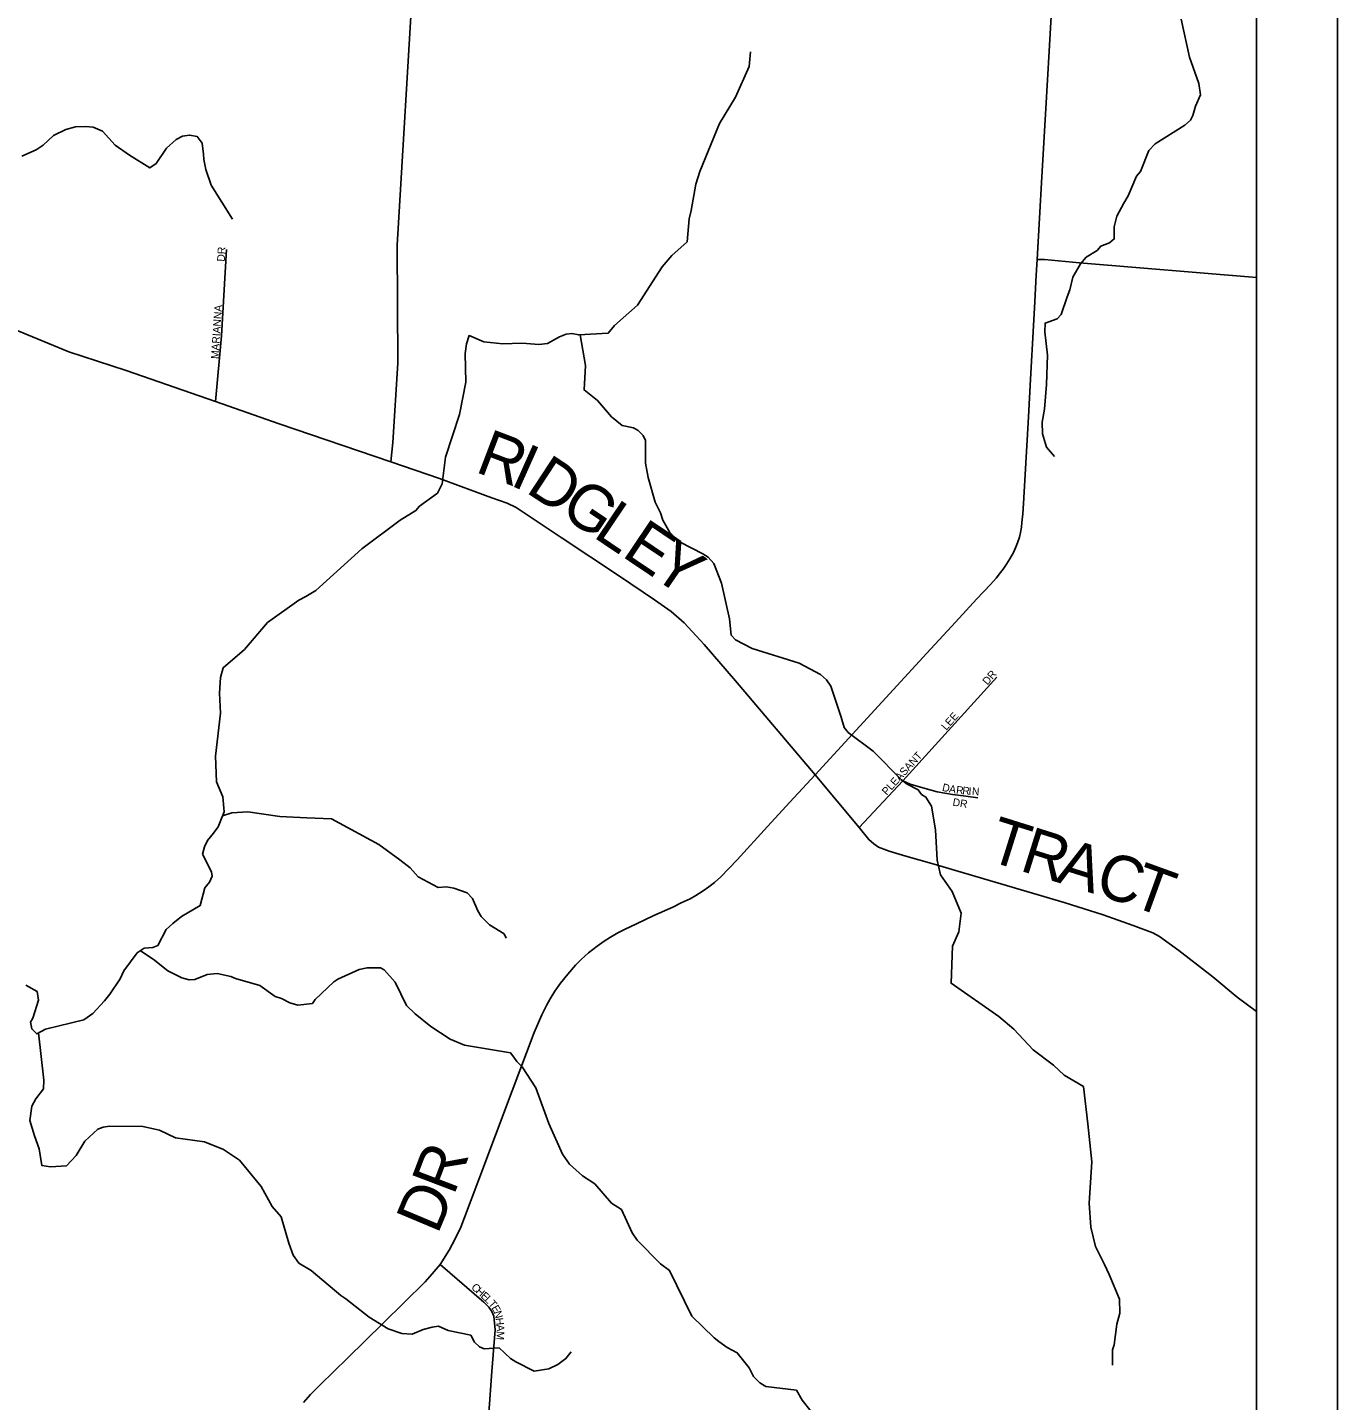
# Model space of a CAD drawing. Extents: x 0 to 40.4, y 0 to 22.
# Drawn here: x 7.886 to 9.5, y 17.508 to 19.2 of the extents above; entities that cross this region are included whole.
import ezdxf

# ---------------------------------------------------------------- set-up
doc = ezdxf.new("R2010")
doc.units = 0
for name, color, linetype in [('GM_X_County_Road', 7, 'Continuous'), ('GM_X_County_Road_Text', 7, 'Continuous'), ('GM_X_Minor_River', 7, 'Continuous'), ('GM_X_Township_Road', 7, 'Continuous'), ('GM_X_Township_Road_Text', 7, 'Continuous'), ('GM_X_Township_Subdivision', 7, 'Continuous'), ('GM_X_Township_Subdivision_Text', 7, 'Continuous'), ('SH_Data', 7, 'Continuous')]:
    doc.layers.add(name, color=color, linetype=linetype)

msp = doc.modelspace()

# ---------------------------------------------------------------- linework, layer by layer
at = {"layer": 'GM_X_County_Road'}
msp.add_lwpolyline([(8.2263, 17.506), (8.2352, 17.5156), (8.247, 17.5274), (8.2806, 17.5605), (8.3247, 17.6035), (8.3765, 17.6543), (8.3851, 17.6645), (8.3949, 17.6757), (8.4059, 17.6937), (8.4133, 17.7075), (8.4201, 17.7219), (8.4248, 17.7339), (8.4425, 17.7806), (8.4836, 17.89), (8.5105, 17.9617), (8.5199, 17.9834), (8.5261, 17.9959), (8.5303, 18.0033), (8.536, 18.0125), (8.5429, 18.0225), (8.5521, 18.0337), (8.5616, 18.0446), (8.5686, 18.0517), (8.5775, 18.0597), (8.588, 18.0681), (8.5968, 18.0743), (8.6045, 18.0792), (8.6136, 18.0844), (8.6217, 18.0887), (8.6366, 18.0957), (8.658, 18.1058), (8.6812, 18.1162), (8.6917, 18.1214), (8.7026, 18.1264), (8.7098, 18.1305), (8.7187, 18.1361), (8.7257, 18.1411), (8.7326, 18.1465), (8.7403, 18.1536), (8.7604, 18.1746), (8.7979, 18.2155), (8.8255, 18.2455), (8.8565, 18.2792), (8.9941, 18.4291), (9.0293, 18.4672), (9.0559, 18.4959), (9.0725, 18.5137), (9.0796, 18.5216), (9.0851, 18.5286), (9.0881, 18.5327), (9.0923, 18.5388), (9.0965, 18.5453), (9.1009, 18.553), (9.1035, 18.559), (9.1057, 18.5651), (9.1081, 18.572), (9.1094, 18.5777), (9.1106, 18.5842), (9.1112, 18.5902), (9.1124, 18.6009), (9.1134, 18.6133), (9.1154, 18.6493), (9.1188, 18.7127), (9.1222, 18.7739), (9.1251, 18.8252), (9.127, 18.8622), (9.129, 18.8948), (9.13, 18.914), (9.1358, 19.016), (9.1406, 19.1001), (9.1449, 19.1707), (9.1485, 19.2357)], dxfattribs=at)
at = {"layer": 'GM_X_Minor_River'}
for points in [[(9.3073, 19.2104), (9.3177, 19.1634), (9.329, 19.1311), (9.3313, 19.1171), (9.3252, 19.1031), (9.3218, 19.0917), (9.3191, 19.086), (9.3119, 19.0796), (9.2756, 19.0565), (9.2676, 19.0486), (9.2573, 19.0224), (9.2524, 19.0167), (9.2422, 18.9925), (9.2368, 18.9834), (9.2281, 18.9675), (9.2251, 18.9542), (9.225, 18.9395), (9.219, 18.9345), (9.2084, 18.9304), (9.2038, 18.9251), (9.1906, 18.9168), (9.1834, 18.9088), (9.1739, 18.8925), (9.1701, 18.8766), (9.1671, 18.8683), (9.1598, 18.8463), (9.1545, 18.841), (9.1398, 18.8357), (9.1394, 18.8251), (9.1427, 18.7963), (9.1415, 18.7603), (9.1392, 18.7299), (9.1361, 18.7137), (9.1368, 18.6992), (9.1417, 18.6829), (9.1515, 18.6715)], [(7.8844, 18.0199), (7.8983, 18.0123), (7.9002, 18.0017), (7.893, 17.9793), (7.8903, 17.9744), (7.8918, 17.9661), (7.8979, 17.96), (7.9088, 17.966), (7.9557, 17.9773), (7.9671, 17.9853), (7.9815, 18.0008), (7.988, 18.0091), (8.0008, 18.028), (8.005, 18.0375), (8.0217, 18.0598), (8.0304, 18.0655), (8.041, 18.0663), (8.0471, 18.0689), (8.0573, 18.0886), (8.0656, 18.0962), (8.0762, 18.1045), (8.0993, 18.1181), (8.105, 18.1401), (8.1107, 18.1469), (8.1141, 18.1545), (8.113, 18.1598), (8.1021, 18.1814), (8.1044, 18.1905), (8.1082, 18.1981), (8.1158, 18.2075), (8.1215, 18.2151), (8.1287, 18.2337), (8.1272, 18.2519), (8.1193, 18.2705), (8.1182, 18.3023), (8.1244, 18.355), (8.1229, 18.38), (8.1241, 18.399), (8.1275, 18.4111), (8.1536, 18.4334), (8.1821, 18.4667), (8.2207, 18.4943), (8.2294, 18.4989), (8.2415, 18.5061), (8.2983, 18.5575), (8.3457, 18.5931), (8.365, 18.6048), (8.3695, 18.6101), (8.3915, 18.6263), (8.3972, 18.6377), (8.4014, 18.6707), (8.4185, 18.723), (8.4265, 18.7628), (8.4255, 18.7984), (8.427, 18.8101), (8.4304, 18.8204), (8.4486, 18.8128), (8.472, 18.8101), (8.4954, 18.8112), (8.5011, 18.8108), (8.5162, 18.8096), (8.5268, 18.8107), (8.5416, 18.819), (8.5499, 18.822), (8.5571, 18.8228), (8.5654, 18.8213), (8.6017, 18.8235), (8.6093, 18.8329), (8.6377, 18.8579), (8.6684, 18.9052), (8.6802, 18.9189), (8.6991, 18.9359), (8.7014, 18.9643), (8.7041, 18.9745), (8.7098, 19.0068), (8.7144, 19.0227), (8.7387, 19.0818), (8.7584, 19.114), (8.7752, 19.1519), (8.7771, 19.17)], [(7.8796, 19.0413), (7.897, 19.0493), (7.9057, 19.0549), (7.9186, 19.067), (7.9337, 19.0742), (7.9455, 19.0776), (7.9583, 19.0779), (7.9674, 19.0772), (7.9787, 19.0722), (7.9946, 19.0551), (8.0123, 19.0426), (8.0372, 19.027), (8.0448, 19.0323), (8.0577, 19.0512), (8.0698, 19.0618), (8.0774, 19.066), (8.0861, 19.0675), (8.0955, 19.0656), (8.1016, 19.0576), (8.1031, 19.0439), (8.1038, 19.0375), (8.1061, 19.025), (8.1128, 19.0056), (8.1392, 18.9639)], [(8.5673, 18.8214), (8.5737, 18.7837), (8.5721, 18.7534), (8.5887, 18.7405), (8.6057, 18.7203), (8.6189, 18.7097), (8.6329, 18.7066), (8.6385, 18.7036), (8.6449, 18.6971), (8.6476, 18.6911), (8.6475, 18.663), (8.6509, 18.6456), (8.6595, 18.6152), (8.6663, 18.6019), (8.6689, 18.5928), (8.6776, 18.5776), (8.6836, 18.5716), (8.6904, 18.5659), (8.7184, 18.5514), (8.7248, 18.5472), (8.732, 18.5396), (8.7414, 18.5153), (8.7511, 18.4713), (8.7533, 18.4512), (8.7586, 18.4455), (8.779, 18.4349), (8.8368, 18.4166), (8.8633, 18.4029), (8.8704, 18.3964), (8.8761, 18.3885), (8.8885, 18.3501), (8.8923, 18.3376), (8.8972, 18.3315), (8.9281, 18.3084), (8.9628, 18.273), (8.97, 18.2677), (8.9836, 18.2609), (8.9877, 18.2548), (8.993, 18.2517), (8.9998, 18.2404), (9.0047, 18.2115), (9.0069, 18.174), (9.011, 18.1558), (9.0253, 18.1353), (9.0366, 18.1087), (9.0335, 18.0856), (9.0256, 18.0682), (9.024, 18.0223), (9.0829, 17.9816), (9.1013, 17.9657), (9.1251, 17.9402), (9.15, 17.9216), (9.1632, 17.9091), (9.187, 17.895), (9.1926, 17.8491), (9.1974, 17.8025), (9.1943, 17.7513), (9.1961, 17.7217), (9.2021, 17.6982), (9.2131, 17.6758), (9.2187, 17.6637), (9.2315, 17.6333), (9.2319, 17.6159), (9.228, 17.6022), (9.225, 17.5768), (9.2227, 17.5708), (9.223, 17.5518)], [(8.1267, 18.2285), (8.1381, 18.2325), (8.1578, 18.2336), (8.1975, 18.2278), (8.2304, 18.2263), (8.261, 18.2251), (8.3191, 18.1935), (8.3452, 18.1745), (8.3577, 18.1646), (8.3678, 18.1536), (8.3924, 18.1403), (8.4026, 18.141), (8.4117, 18.1395), (8.4279, 18.1338), (8.4347, 18.1269), (8.4411, 18.1117), (8.4453, 18.1045), (8.4554, 18.0943), (8.4736, 18.0832), (8.4762, 18.0779)], [(8.0255, 18.0623), (8.0413, 18.0522), (8.0595, 18.0378), (8.0765, 18.029), (8.0855, 18.0264), (8.0927, 18.0271), (8.1079, 18.0331), (8.12, 18.0346), (8.137, 18.0308), (8.1426, 18.0281), (8.1725, 18.0197), (8.1917, 18.0061), (8.1993, 18.0038), (8.2095, 17.9981), (8.2193, 17.9954), (8.2375, 17.9973), (8.2409, 18.0022), (8.2636, 18.0241), (8.2689, 18.0275), (8.295, 18.0392), (8.3049, 18.0415), (8.3211, 18.0415), (8.326, 18.0388), (8.3392, 18.0236), (8.3535, 17.9951), (8.3641, 17.9845), (8.3834, 17.9693), (8.4071, 17.9533), (8.4249, 17.9461), (8.4816, 17.9365), (8.4857, 17.9312), (8.4891, 17.9259), (8.4956, 17.9194), (8.5125, 17.8936), (8.5287, 17.8496), (8.5456, 17.8116), (8.5539, 17.7995), (8.5701, 17.7851), (8.5853, 17.7752), (8.6056, 17.7516), (8.6181, 17.7436), (8.6313, 17.7148), (8.6373, 17.7057), (8.666, 17.6768), (8.6773, 17.6685), (8.7048, 17.6123), (8.7323, 17.5853), (8.738, 17.5811), (8.7482, 17.5735), (8.7606, 17.5671), (8.7754, 17.5485), (8.7806, 17.5378), (8.7886, 17.5299), (8.7957, 17.5257), (8.8335, 17.5211), (8.8407, 17.5085), (8.8516, 17.4949)], [(7.9001, 17.9612), (7.9068, 17.9031), (7.9064, 17.8925), (7.8966, 17.88), (7.892, 17.8709), (7.8893, 17.8531), (7.8953, 17.8345), (7.901, 17.8182), (7.9043, 17.7977), (7.9149, 17.7962), (7.9346, 17.7976), (7.9463, 17.8101), (7.957, 17.8279), (7.9732, 17.8427), (7.9797, 17.845), (7.9876, 17.8465), (8.0285, 17.846), (8.0492, 17.8414), (8.0689, 17.8319), (8.1044, 17.8269), (8.1278, 17.8177), (8.1475, 17.8044), (8.1743, 17.7718), (8.1878, 17.7475), (8.1991, 17.7346), (8.2085, 17.702), (8.2138, 17.6875), (8.2206, 17.6777), (8.2357, 17.6685), (8.2723, 17.6378), (8.2787, 17.6336), (8.3074, 17.6108), (8.3308, 17.5967), (8.3474, 17.591), (8.3603, 17.5902), (8.3739, 17.5959), (8.3849, 17.5985), (8.3928, 17.6), (8.4045, 17.5947), (8.4325, 17.5889), (8.437, 17.5802), (8.4431, 17.5745), (8.4491, 17.5718), (8.4673, 17.5733), (8.4816, 17.56), (8.488, 17.5558), (8.5107, 17.5444), (8.5288, 17.5474), (8.5398, 17.5527), (8.5497, 17.5599), (8.5561, 17.5682)]]:
    msp.add_lwpolyline(points, dxfattribs=at)
at = {"layer": 'GM_X_Township_Road'}
for points in [[(8.362, 19.2688), (8.3417, 18.9317), (8.3427, 18.7864), (8.3364, 18.6887), (8.3339, 18.6648)], [(9.4, 18.8918), (9.182, 18.9101), (9.1391, 18.914), (9.13, 18.914)], [(7.8738, 18.8268), (7.9375, 18.8004), (8.0082, 18.7774), (8.1182, 18.7393), (8.1966, 18.7116), (8.3339, 18.6648), (8.3941, 18.6444), (8.4586, 18.6206), (8.4773, 18.614), (8.4884, 18.6085), (8.5057, 18.597), (8.5437, 18.5714), (8.6157, 18.524), (8.6588, 18.4948), (8.6793, 18.4804), (8.6952, 18.4666), (8.7198, 18.4396), (8.7584, 18.3949), (8.8565, 18.2792)], [(8.8565, 18.2792), (8.9109, 18.2142), (8.9226, 18.1995), (8.9287, 18.194), (8.9346, 18.1901), (8.9477, 18.185), (8.9685, 18.1789), (9.0005, 18.1698), (9.1633, 18.122), (9.2113, 18.1066), (9.2485, 18.0937), (9.2725, 18.0845), (9.2807, 18.0798), (9.3046, 18.0628), (9.3463, 18.0303), (9.3762, 18.0054), (9.4, 17.9876)]]:
    msp.add_lwpolyline(points, dxfattribs=at)
at = {"layer": 'GM_X_Township_Subdivision'}
for points in [[(8.1182, 18.7393), (8.1255, 18.8201), (8.1318, 18.9266)], [(8.9109, 18.2142), (8.9645, 18.2717), (9.0803, 18.3994)], [(8.9645, 18.2717), (8.9736, 18.2676), (8.9923, 18.2622), (9.0067, 18.2583), (9.0258, 18.2548), (9.0424, 18.2528), (9.0569, 18.251)], [(8.5424, 17.2763), (8.5332, 17.2776), (8.5221, 17.2779), (8.4856, 17.2794), (8.4716, 17.2806), (8.4634, 17.282), (8.4574, 17.2844), (8.452, 17.2874), (8.4444, 17.2978), (8.4416, 17.3078), (8.4421, 17.3182), (8.4466, 17.379), (8.4584, 17.5441), (8.4624, 17.5953), (8.4608, 17.6121), (8.4583, 17.6179), (8.4548, 17.6233), (8.4485, 17.6293), (8.3949, 17.6757)]]:
    msp.add_lwpolyline(points, dxfattribs=at)
at = {"layer": 'SH_Data'}
for p, q in [((9.5, 21), (9.5, 14)), ((9.4, 20.9), (9.4, 14.1))]:
    msp.add_line(p, q, dxfattribs=at)

# ---------------------------------------------------------------- texts
at = {"layer": 'GM_X_County_Road_Text'}
for s, rotation, p in [('R', 69.1691, (8.4115, 17.7598)), ('D', 67.2238, (8.3914, 17.7118))]:
    msp.add_text(s, height=0.0568, rotation=rotation, dxfattribs=at).set_placement(p)
at = {"layer": 'GM_X_Township_Road_Text'}
for s, rotation, p in [('R', 339.1379, (8.4365, 18.653)), ('I', 335.9353, (8.4794, 18.6367)), ('D', 326.7161, (8.4986, 18.6283)), ('G', 326.0776, (8.5402, 18.601)), ('L', 326.0824, (8.5817, 18.5731)), ('E', 326.0782, (8.617, 18.5494)), ('Y', 325.6007, (8.6521, 18.5257)), ('T', 342.5544, (9.0665, 18.1744)), ('R', 342.5561, (9.107, 18.1617)), ('A', 342.5558, (9.1515, 18.1477)), ('C', 342.4204, (9.1992, 18.1327)), ('T', 340.085, (9.2431, 18.1188))]:
    msp.add_text(s, height=0.0568, rotation=rotation, dxfattribs=at).set_placement(p)
at = {"layer": 'GM_X_Township_Subdivision_Text'}
for s, rotation, p in [('DR', 86.8222, (8.1294, 18.9113)), ('MARIANNA', 86.2846, (8.1219, 18.7913)), ('DR', 49.3961, (9.0689, 18.3891)), ('LEE', 48.5061, (9.0181, 18.3333)), ('PLEASANT', 47.7794, (8.9448, 18.2533)), ('D', 346.9022, (9.0124, 18.2596)), ('A', 349.9328, (9.021, 18.2576)), ('R', 353.6918, (9.0299, 18.2561)), ('R', 355.0554, (9.0376, 18.2552)), ('I', 356.488, (9.0453, 18.2546)), ('N', 356.784, (9.0495, 18.2543)), ('DR', 350.5416, (9.0254, 18.2413)), ('C', 317.7655, (8.4323, 17.6467)), ('H', 317.7733, (8.4379, 17.6417)), ('E', 317.7776, (8.444, 17.6361)), ('L', 315.058, (8.4489, 17.6317)), ('T', 310.4946, (8.4535, 17.6271)), ('E', 300.4905, (8.4576, 17.6224)), ('N', 286.9212, (8.4607, 17.6172)), ('H', 276.4826, (8.463, 17.6097)), ('A', 273.061, (8.464, 17.6016)), ('M', 268.0508, (8.4644, 17.5935))]:
    msp.add_text(s, height=0.00947, rotation=rotation, dxfattribs=at).set_placement(p)

doc.saveas('drawing.dxf')
